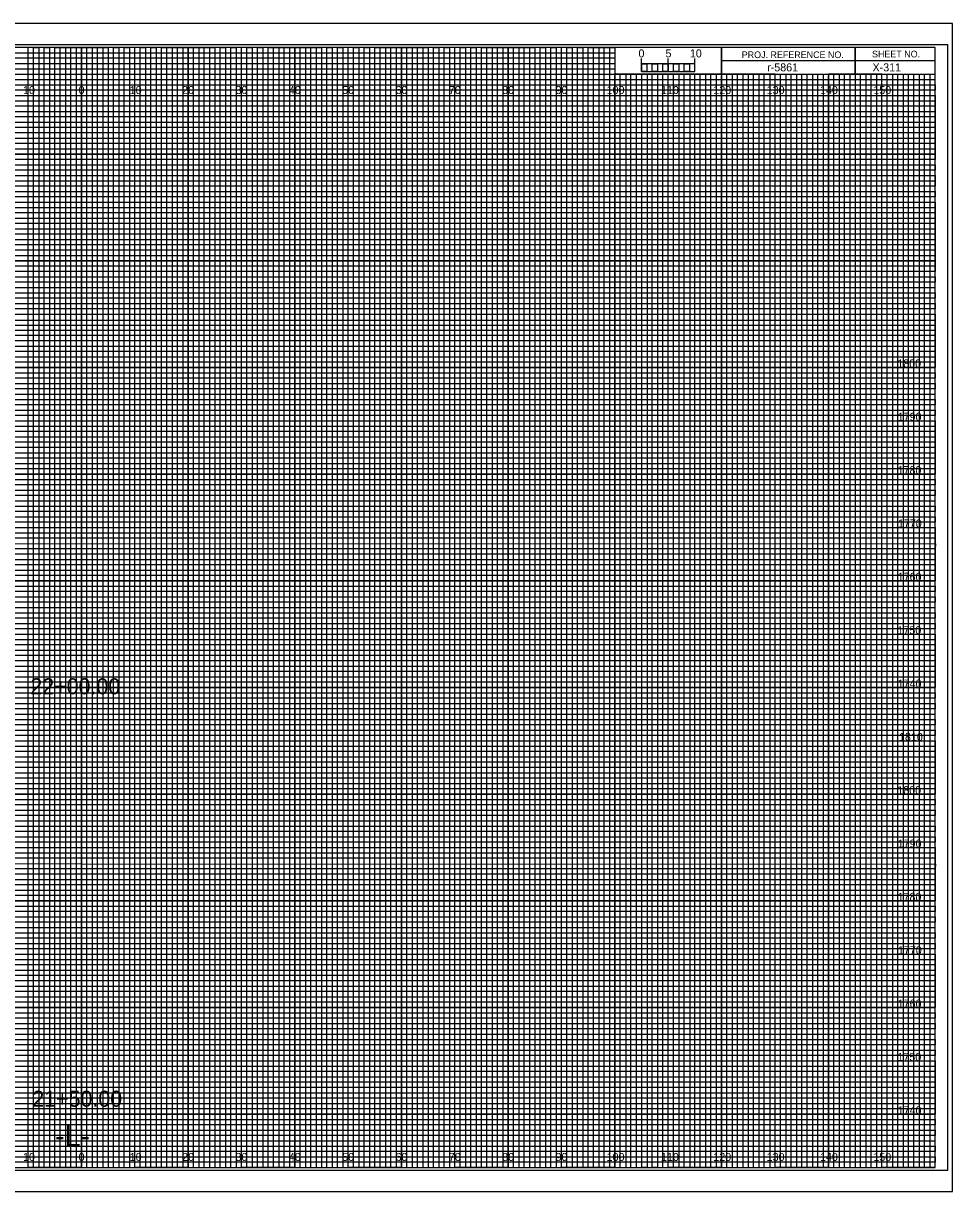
# Model space of a CAD drawing. Extents: x -15 to 323, y -5 to 6170.
# Drawn here: x 149.1 to 323.3, y 1535.5 to 1754.5 of the extents above; entities that cross this region are included whole.
import ezdxf

# ---------------------------------------------------------------- set-up
doc = ezdxf.new("R2010")
doc.units = 0
for name, color, linetype in [('Prop XS Alignment Label', 7, 'Continuous'), ('Prop XS Bar Scale Labels', 7, 'Continuous'), ('Prop XS DDE', 7, 'Continuous'), ('Prop XS DDE Earthwork Shape', 7, 'Continuous'), ('Prop XS DDE Slope Text', 7, 'Continuous'), ('Prop XS DDE Text', 7, 'Continuous'), ('Prop XS Earthwork Shape', 7, 'Continuous'), ('Prop XS Noise Wall', 7, 'Continuous'), ('Prop XS Project Number', 7, 'Continuous'), ('Prop XS Retaining Wall', 7, 'Continuous'), ('Prop XS Station Labels', 7, 'Continuous'), ('Prop XS Temporary Shoring', 7, 'Continuous'), ('Scratch_Level_3', 7, 'Continuous'), ('Scratch_Level_7', 7, 'Continuous'), ('Scratch_Level_8', 7, 'Continuous'), ('Sheet Cross Section Grid Minor 1 CELL', 7, 'Continuous')]:
    doc.layers.add(name, color=color, linetype=linetype)

msp = doc.modelspace()

# ---------------------------------------------------------------- linework, layer by layer
at = {"layer": 'Prop XS Alignment Label'}
for p, q in [((265, 1745.49), (265, 1747.9)), ((265, 1746.9), (265, 1747.9)), ((270, 1745.49), (270, 1747.9)), ((275, 1745.49), (275, 1747.9)), ((275, 1746.9), (275, 1747.9))]:
    msp.add_line(p, q, dxfattribs=at)
for points in [[(275, 1746.9), (265, 1746.9), (265, 1745.49), (275, 1745.49)], [(265, 1746.9), (266, 1746.9), (266, 1745.49), (265, 1745.49)], [(267, 1746.9), (268, 1746.9), (268, 1745.49), (267, 1745.49)], [(269, 1746.9), (270, 1746.9), (270, 1745.49), (269, 1745.49)], [(271, 1746.9), (272, 1746.9), (272, 1745.49), (271, 1745.49)], [(273, 1746.9), (274, 1746.9), (274, 1745.49), (273, 1745.49)]]:
    msp.add_lwpolyline(points, close=True, dxfattribs=at)
at = {"layer": 'Prop XS DDE'}
msp.add_lwpolyline([(-13.4, 1535.5), (323.3, 1535.5), (323.3, 1754.5), (-13.4, 1754.5)], close=True, dxfattribs=at)
at = {"layer": 'Prop XS DDE Slope Text'}
msp.add_lwpolyline([(-10.8, 1539.5), (322.4, 1539.5), (322.4, 1750.5), (-10.8, 1750.5)], close=True, dxfattribs=at)
at = {"layer": 'Prop XS DDE Text'}
for p, q in [((150, 1540), (150, 1750)), ((160, 1540), (160, 1750)), ((170, 1540), (170, 1750)), ((180, 1540), (180, 1750)), ((190, 1540), (190, 1750)), ((200, 1540), (200, 1750)), ((210, 1540), (210, 1750)), ((220, 1540), (220, 1750)), ((230, 1540), (230, 1750)), ((240, 1540), (240, 1750)), ((250, 1540), (250, 1750)), ((260, 1540), (260, 1744.69)), ((270, 1540), (270, 1744.69)), ((280, 1540), (280, 1744.69)), ((290, 1540), (290, 1744.69)), ((300, 1540), (300, 1744.69)), ((310, 1540), (310, 1744.69)), ((0, 1740), (320, 1740)), ((0, 1730), (320, 1730)), ((0, 1720), (320, 1720)), ((0, 1710), (320, 1710)), ((0, 1700), (320, 1700)), ((0, 1690), (320, 1690)), ((0, 1680), (320, 1680)), ((0, 1670), (320, 1670)), ((0, 1660), (320, 1660)), ((0, 1650), (320, 1650)), ((0, 1640), (320, 1640)), ((0, 1630), (320, 1630)), ((0, 1620), (320, 1620)), ((0, 1610), (320, 1610)), ((0, 1600), (320, 1600)), ((0, 1590), (320, 1590)), ((0, 1580), (320, 1580)), ((0, 1570), (320, 1570)), ((0, 1560), (320, 1560)), ((0, 1550), (320, 1550))]:
    msp.add_line(p, q, dxfattribs=at)
at = {"layer": 'Prop XS Earthwork Shape'}
for p, q in [((150, 1750), (140, 1750)), ((150, 1540), (150, 1750)), ((170, 1750), (160, 1750)), ((160, 1750), (160, 1540)), ((170, 1540), (170, 1750)), ((190, 1750), (180, 1750)), ((180, 1750), (180, 1540)), ((190, 1540), (190, 1750)), ((210, 1750), (200, 1750)), ((200, 1750), (200, 1540)), ((210, 1540), (210, 1750)), ((230, 1750), (220, 1750)), ((220, 1750), (220, 1540)), ((230, 1540), (230, 1750)), ((250, 1750), (240, 1750)), ((240, 1750), (240, 1540)), ((250, 1540), (250, 1750)), ((260, 1750), (260, 1540)), ((270, 1540), (270, 1745)), ((290, 1745), (280, 1745)), ((280, 1745), (280, 1540)), ((290, 1540), (290, 1745)), ((310, 1745), (300, 1745)), ((300, 1745), (300, 1540)), ((310, 1540), (310, 1745)), ((160, 1540), (150, 1540)), ((180, 1540), (170, 1540)), ((200, 1540), (190, 1540)), ((220, 1540), (210, 1540)), ((240, 1540), (230, 1540)), ((260, 1540), (250, 1540)), ((280, 1540), (270, 1540)), ((300, 1540), (290, 1540)), ((320, 1540), (310, 1540)), ((320, 1540), (320, 1540))]:
    msp.add_line(p, q, dxfattribs=at)
for points in [[(0, 1740), (320, 1740), (320, 1730), (0, 1730)], [(0, 1720), (320, 1720), (320, 1710), (0, 1710)], [(0, 1700), (320, 1700), (320, 1690), (0, 1690)], [(0, 1680), (320, 1680), (320, 1670), (0, 1670)], [(0, 1660), (320, 1660), (320, 1650), (0, 1650)], [(0, 1640), (320, 1640), (320, 1630), (0, 1630)], [(0, 1620), (320, 1620), (320, 1610), (0, 1610)], [(0, 1600), (320, 1600), (320, 1590), (0, 1590)], [(0, 1580), (320, 1580), (320, 1570), (0, 1570)], [(0, 1560), (320, 1560), (320, 1550), (0, 1550)]]:
    msp.add_lwpolyline(points, dxfattribs=at)
at = {"layer": 'Prop XS Noise Wall'}
for p, q in [((305, 1750), (305, 1745)), ((305, 1745), (305, 1750)), ((280, 1747.5), (280, 1745)), ((320, 1747.49), (280, 1747.49)), ((280, 1745), (320, 1745))]:
    msp.add_line(p, q, dxfattribs=at)
for points in [[(320, 1750), (0, 1750), (0, 1540), (320, 1540)], [(280, 1750), (260, 1750), (260, 1745.03), (280, 1745.03)], [(320, 1750), (280, 1750), (280, 1745), (320, 1745)]]:
    msp.add_lwpolyline(points, close=True, dxfattribs=at)
at = {"layer": 'Prop XS Retaining Wall'}
for p, q in [((267, 1745), (266.01, 1745)), ((266.01, 1745), (266.01, 1540)), ((267, 1540), (267, 1745)), ((269, 1745), (268, 1745)), ((268, 1745), (268, 1540)), ((269, 1540), (269, 1745)), ((266.01, 1540), (265, 1540)), ((268, 1540), (267, 1540))]:
    msp.add_line(p, q, dxfattribs=at)
for points in [[(150, 1540), (151, 1540), (151, 1750), (152, 1750), (152, 1540)], [(152, 1540), (153, 1540), (153, 1750), (154, 1750), (154, 1540)], [(155, 1540), (156, 1540), (156, 1750), (157, 1750), (157, 1540)], [(157, 1540), (158, 1540), (158, 1750), (159, 1750), (159, 1540)], [(160, 1540), (161, 1540), (161, 1750), (162, 1750), (162, 1540)], [(162, 1540), (163, 1540), (163, 1750), (164, 1750), (164, 1540)], [(165, 1540), (166, 1540), (166, 1750), (167, 1750), (167, 1540)], [(167, 1540), (168, 1540), (168, 1750), (169, 1750), (169, 1540)], [(170, 1540), (171, 1540), (171, 1750), (172, 1750), (172, 1540)], [(172, 1540), (173, 1540), (173, 1750), (174, 1750), (174, 1540)], [(175, 1540), (176, 1540), (176, 1750), (177, 1750), (177, 1540)], [(177, 1540), (178, 1540), (178, 1750), (179, 1750), (179, 1540)], [(180, 1540), (181, 1540), (181, 1750), (182, 1750), (182, 1540)], [(182, 1540), (183, 1540), (183, 1750), (184, 1750), (184, 1540)], [(185, 1540), (186, 1540), (186, 1750), (187, 1750), (187, 1540)], [(187, 1540), (188, 1540), (188, 1750), (189, 1750), (189, 1540)], [(190, 1540), (191, 1540), (191, 1750), (192, 1750), (192, 1540)], [(192, 1540), (193, 1540), (193, 1750), (194, 1750), (194, 1540)], [(195, 1540), (196, 1540), (196, 1750), (197, 1750), (197, 1540)], [(197, 1540), (198, 1540), (198, 1750), (199, 1750), (199, 1540)], [(200, 1540), (201, 1540), (201, 1750), (202, 1750), (202, 1540)], [(202, 1540), (203, 1540), (203, 1750), (204, 1750), (204, 1540)], [(205, 1540), (206, 1540), (206, 1750), (207, 1750), (207, 1540)], [(207, 1540), (208, 1540), (208, 1750), (209, 1750), (209, 1540)], [(210, 1540), (211, 1540), (211, 1750), (212, 1750), (212, 1540)], [(212, 1540), (213, 1540), (213, 1750), (214, 1750), (214, 1540)], [(215, 1540), (216, 1540), (216, 1750), (217, 1750), (217, 1540)], [(217, 1540), (218, 1540), (218, 1750), (219, 1750), (219, 1540)], [(220, 1540), (221, 1540), (221, 1750), (222, 1750), (222, 1540)], [(222, 1540), (223, 1540), (223, 1750), (224, 1750), (224, 1540)], [(225, 1540), (226, 1540), (226, 1750), (227, 1750), (227, 1540)], [(227, 1540), (228, 1540), (228, 1750), (229, 1750), (229, 1540)], [(230, 1540), (231, 1540), (231, 1750), (232, 1750), (232, 1540)], [(232, 1540), (233, 1540), (233, 1750), (234, 1750), (234, 1540)], [(235, 1540), (236, 1540), (236, 1750), (237, 1750), (237, 1540)], [(237, 1540), (238, 1540), (238, 1750), (239, 1750), (239, 1540)], [(240, 1540), (241, 1540), (241, 1750), (242, 1750), (242, 1540)], [(242, 1540), (243, 1540), (243, 1750), (244, 1750), (244, 1540)], [(245, 1540), (246, 1540), (246, 1750), (247, 1750), (247, 1540)], [(247, 1540), (248, 1540), (248, 1750), (249, 1750), (249, 1540)], [(250, 1540), (251, 1540), (251, 1750), (252, 1750), (252, 1540)], [(252, 1540), (253, 1540), (253, 1750), (254, 1750), (254, 1540)], [(255, 1540), (256, 1540), (256, 1750), (257, 1750), (257, 1540)], [(257, 1540), (258, 1540), (258, 1750), (259, 1750), (259, 1540)], [(260, 1540), (261, 1540), (261, 1745), (262.02, 1745), (262.02, 1540)], [(262, 1540), (263, 1540), (263, 1745), (263.99, 1745), (263.99, 1540)], [(270, 1540), (270.98, 1540), (270.98, 1745), (272, 1745), (272, 1540)], [(272, 1540), (273, 1540), (273, 1745), (274.05, 1745), (274.05, 1540)], [(275, 1540), (276, 1540), (276, 1745), (277, 1745), (277, 1540)], [(277, 1540), (278, 1540), (278, 1745), (279, 1745), (279, 1540)], [(280, 1540), (281, 1540), (281, 1745), (282, 1745), (282, 1540)], [(282, 1540), (283, 1540), (283, 1745), (284, 1745), (284, 1540)], [(285, 1540), (286, 1540), (286, 1745), (287, 1745), (287, 1540)], [(287, 1540), (288, 1540), (288, 1745), (289, 1745), (289, 1540)], [(290, 1540), (291, 1540), (291, 1745), (292, 1745), (292, 1540)], [(292, 1540), (293, 1540), (293, 1745), (294, 1745), (294, 1540)], [(295, 1540), (296, 1540), (296, 1745), (297, 1745), (297, 1540)], [(297, 1540), (298, 1540), (298, 1745), (299, 1745), (299, 1540)], [(300, 1540), (301, 1540), (301, 1745), (302, 1745), (302, 1540)], [(302, 1540), (303, 1540), (303, 1745), (304, 1745), (304, 1540)], [(305, 1540), (306, 1540), (306, 1745), (307, 1745), (307, 1540)], [(307, 1540), (308, 1540), (308, 1745), (309, 1745), (309, 1540)], [(310, 1540), (311, 1540), (311, 1745), (312, 1745), (312, 1540)], [(312, 1540), (313, 1540), (313, 1745), (314, 1745), (314, 1540)], [(315, 1540), (316, 1540), (316, 1745), (317, 1745), (317, 1540)], [(317, 1540), (318, 1540), (318, 1745), (319, 1745), (319, 1540)]]:
    msp.add_lwpolyline(points, dxfattribs=at)
at = {"layer": 'Prop XS Station Labels'}
for points in [[(145, 1540), (155, 1540), (155, 1750), (165, 1750), (165, 1540), (175, 1540), (175, 1750), (185, 1750), (185, 1540), (195, 1540), (195, 1750), (205, 1750), (205, 1540), (215, 1540), (215, 1750), (225, 1750), (225, 1540), (235, 1540), (235, 1750), (245, 1750), (245, 1540), (255, 1540), (255, 1750), (259.93, 1750), (260, 1750), (260, 1745), (264.99, 1745), (264.99, 1540), (275, 1540), (275, 1745), (285, 1745), (285, 1540), (295, 1540), (295, 1745), (305, 1745), (305, 1540), (315, 1540), (315, 1745)], [(0, 1745), (275, 1745)], [(0, 1725), (320, 1725), (320, 1735), (0, 1735)], [(0, 1705), (320, 1705), (320, 1715), (0, 1715)], [(0, 1685), (320, 1685), (320, 1695), (0, 1695)], [(0, 1665), (320, 1665), (320, 1675), (0, 1675)], [(0, 1645), (320, 1645), (320, 1655), (0, 1655)], [(0, 1625), (320, 1625), (320, 1635), (0, 1635)], [(0, 1605), (320, 1605), (320, 1615), (0, 1615)], [(0, 1585), (320, 1585), (320, 1595), (0, 1595)], [(0, 1565), (320, 1565), (320, 1575), (0, 1575)], [(0, 1545), (320, 1545), (320, 1555), (0, 1555)]]:
    msp.add_lwpolyline(points, dxfattribs=at)
at = {"layer": 'Scratch_Level_7'}
for p, q in [((323.3, 1754.5), (-13.4, 1754.5)), ((-13.4, 1535.5), (323.3, 1535.5))]:
    msp.add_line(p, q, dxfattribs=at)
at = {"layer": 'Sheet Cross Section Grid Minor 1 CELL'}
for p, q in [((0, 1749), (260, 1749)), ((260, 1747.98), (0, 1747.98)), ((260, 1749), (260, 1747.98)), ((0, 1747), (260, 1747)), ((260, 1745.89), (0, 1745.89)), ((260, 1747), (260, 1745.89)), ((0, 1744), (320, 1744))]:
    msp.add_line(p, q, dxfattribs=at)
for points in [[(0, 1743), (270, 1743), (320, 1743), (320, 1742), (0, 1742)], [(0, 1741), (320, 1741), (320, 1739), (0, 1739)], [(0, 1738), (320, 1738), (320, 1737), (0, 1736.98)], [(0, 1736), (320, 1736), (320, 1734), (0, 1734)], [(0, 1733), (320, 1733), (320, 1732), (0, 1732)], [(0, 1731), (320, 1731), (320, 1729), (0, 1729)], [(0, 1728), (320, 1728), (320, 1727), (0, 1727)], [(0, 1726), (320, 1726), (320, 1724), (0, 1724)], [(0, 1723), (320, 1723), (320, 1722), (0, 1722)], [(0, 1721), (320, 1721), (320, 1719), (0, 1719)], [(0, 1718), (320, 1718), (320, 1717), (0, 1717)], [(0, 1716), (320, 1716), (320, 1713.95), (320, 1713), (320, 1712), (0, 1712)], [(0, 1714), (320, 1714), (320, 1713), (0, 1713)], [(0, 1711), (320, 1711), (320, 1709), (0, 1709.03)], [(0, 1709.03), (320, 1709), (320, 1708), (0, 1708)], [(0, 1707), (320, 1707), (320, 1706), (0, 1706)], [(0, 1704), (320, 1704), (320, 1703), (0, 1703)], [(0, 1702), (320, 1702), (320, 1701), (0, 1701)], [(-0.07, 1698.89), (320, 1698.89), (320, 1697.88), (-0.07, 1697.88)], [(0, 1697), (320, 1697), (320, 1696), (0, 1696)], [(0, 1694), (320, 1694), (320, 1693), (0, 1693)], [(0, 1692), (320, 1692), (320, 1691), (0, 1691)], [(0, 1689), (320, 1689), (320, 1688), (0, 1688)], [(0, 1687), (320, 1687), (320, 1686), (0, 1686)], [(0, 1684), (320, 1684), (320, 1683), (0, 1683)], [(0, 1682), (320, 1682), (320, 1681), (0, 1681)], [(0, 1679), (320, 1679), (319.99, 1677.98), (0, 1678)], [(0, 1677), (320, 1677), (320, 1676), (0, 1676)], [(0, 1674), (320, 1674), (320, 1673), (0, 1673)], [(0, 1672), (320, 1672), (320, 1671), (0, 1671)], [(0, 1669), (320, 1669), (320, 1668), (0, 1668)], [(0, 1667), (320, 1667), (320, 1666), (0, 1666)], [(0, 1664), (320, 1664), (320, 1663), (0, 1663)], [(0, 1662), (320, 1662), (320, 1661), (0, 1661)], [(0, 1659), (320, 1659), (320, 1658), (0, 1658)], [(0, 1656.99), (320.07, 1656.91), (320, 1656), (0, 1656)], [(0, 1654), (320, 1654), (320, 1653), (0, 1653)], [(0, 1652), (320, 1652), (320, 1651), (0, 1651)], [(0, 1649), (320, 1649), (320, 1648), (0, 1648)], [(0, 1647), (320, 1647), (320, 1646), (0, 1646)], [(0, 1644), (320, 1644), (320, 1643), (0, 1643)], [(0, 1642), (320, 1642), (320, 1641), (0, 1641)], [(0, 1639), (320, 1639), (320, 1638), (0, 1638)], [(0, 1637), (320, 1637), (320, 1636), (0, 1636)], [(0, 1634), (320, 1634), (320, 1633), (0, 1633)], [(0, 1632), (320, 1632), (320, 1631), (0, 1631)], [(0, 1629), (320, 1629), (320, 1628), (0, 1628)], [(0, 1627), (320, 1627), (320, 1626), (0, 1626)], [(0, 1624), (320, 1624), (320, 1623), (0, 1623)], [(0, 1622), (320, 1622), (320, 1621), (0, 1621)], [(0, 1619), (320, 1619), (319.99, 1617.98), (0, 1618)], [(0, 1617), (320, 1617), (320, 1616), (0, 1616)], [(0, 1614), (320, 1614), (320, 1613), (0, 1613)], [(0, 1612), (320, 1612), (320, 1611), (0, 1611)], [(0, 1609), (320, 1609), (320, 1608), (0, 1608)], [(0, 1607), (320, 1607), (320, 1606), (0, 1606)], [(0, 1604), (320, 1604), (320, 1603), (0, 1603)], [(0, 1602), (320, 1602), (320, 1601), (0, 1601)], [(0, 1599), (320, 1599), (320, 1598), (0, 1598)], [(0, 1596.99), (320.07, 1596.91), (320, 1596), (0, 1596)], [(0, 1594), (320, 1594), (320, 1593), (0, 1593)], [(0, 1592), (320, 1592), (320, 1591), (0, 1591)], [(0, 1589), (320, 1589), (320, 1588), (0, 1588)], [(0, 1587), (320, 1587), (320, 1586), (0, 1586)], [(0, 1584), (320, 1584), (320, 1583), (0, 1583)], [(0, 1582), (320, 1582), (320, 1581), (0, 1581)], [(0, 1579), (320, 1579), (320, 1578), (0, 1578)], [(0, 1577), (320, 1577), (320, 1576), (0, 1576)], [(0, 1574), (320, 1574), (320, 1573), (0, 1573)], [(0, 1572), (320, 1572), (320, 1571), (0, 1571)], [(0, 1569), (320, 1569), (320, 1568), (0, 1568)], [(0, 1567), (320, 1567), (320, 1566), (0, 1566)], [(0, 1564), (320, 1564), (320, 1563), (0, 1563)], [(0, 1562), (320, 1562), (320, 1561), (0, 1561)], [(0, 1559), (320, 1559), (320, 1558), (0, 1558)], [(0, 1557), (320, 1557), (320, 1556), (0, 1556)], [(0, 1554), (320, 1554), (320, 1553), (0, 1553)], [(0, 1552), (320, 1552), (320, 1551), (0, 1551)], [(0, 1549), (320, 1549), (320, 1548), (0, 1548)], [(0, 1547), (320, 1547), (320, 1546), (0, 1546)], [(0, 1544), (320, 1544), (320, 1543), (0, 1543)], [(0, 1542), (320, 1542), (320, 1541), (0, 1541)]]:
    msp.add_lwpolyline(points, dxfattribs=at)

# ---------------------------------------------------------------- texts
at = {"layer": 'Prop XS Alignment Label'}
for s, height, p in [('0', 1.5, (264.41, 1748.12)), ('-L-', 4, (155.06, 1544))]:
    msp.add_text(s, height=height, dxfattribs=at).set_placement(p)
at = {"layer": 'Prop XS Bar Scale Labels'}
for s, p in [('5', (269.47, 1748.12)), ('10', (274.04, 1748.12))]:
    msp.add_text(s, height=1.5, dxfattribs=at).set_placement(p)
at = {"layer": 'Prop XS DDE Earthwork Shape'}
msp.add_text('X-311', height=1.5, dxfattribs=at).set_placement((308.28, 1745.5))
at = {"layer": 'Prop XS Noise Wall'}
for s, p in [('PROJ. REFERENCE NO.', (283.77, 1747.99)), ('SHEET NO.', (308.19, 1748.12))]:
    msp.add_text(s, height=1.25, dxfattribs=at).set_placement(p)
at = {"layer": 'Prop XS Project Number'}
msp.add_text('r-5861', height=1.5, dxfattribs=at).set_placement((288.53, 1745.5))
at = {"layer": 'Prop XS Temporary Shoring'}
for s, p in [('22+00.00', (150.41, 1628.73)), ('21+50.00', (150.77, 1551.42))]:
    msp.add_text(s, height=3, dxfattribs=at).set_placement(p)
at = {"layer": 'Scratch_Level_3'}
for s, p in [('1800', (312.92, 1690)), ('1790', (313, 1680)), ('1780', (312.98, 1670)), ('1770', (313.04, 1660)), ('1760', (313, 1650)), ('1750', (312.96, 1640)), ('1740', (313, 1630)), ('1810', (313.25, 1620)), ('1800', (312.92, 1610)), ('1790', (313, 1600)), ('1780', (312.98, 1590)), ('1770', (313.04, 1580)), ('1760', (313, 1570)), ('1750', (312.96, 1560)), ('1740', (313, 1550))]:
    msp.add_text(s, height=1.5, dxfattribs=at).set_placement(p)
at = {"layer": 'Scratch_Level_8'}
for s, p in [('10', (149.04, 1741.25)), ('0', (159.45, 1741.25)), ('0', (159.45, 1741.25)), ('10', (169.04, 1741.25)), ('20', (178.86, 1741.25)), ('30', (188.86, 1741.25)), ('40', (198.86, 1741.25)), ('50', (208.86, 1741.25)), ('60', (218.86, 1741.25)), ('70', (228.86, 1741.25)), ('80', (238.86, 1741.25)), ('90', (248.86, 1741.25)), ('100', (258.44, 1741.25)), ('110', (268.62, 1741.25)), ('120', (278.44, 1741.25)), ('130', (288.44, 1741.25)), ('140', (298.44, 1741.25)), ('150', (308.44, 1741.25)), ('10', (149.04, 1541.25)), ('0', (159.45, 1541.25)), ('0', (159.45, 1541.25)), ('10', (169.04, 1541.25)), ('20', (178.86, 1541.25)), ('30', (188.86, 1541.25)), ('40', (198.86, 1541.25)), ('50', (208.86, 1541.25)), ('60', (218.86, 1541.25)), ('70', (228.86, 1541.25)), ('80', (238.86, 1541.25)), ('90', (248.86, 1541.25)), ('100', (258.44, 1541.25)), ('110', (268.62, 1541.25)), ('120', (278.44, 1541.25)), ('130', (288.44, 1541.25)), ('140', (298.44, 1541.25)), ('150', (308.44, 1541.25))]:
    msp.add_text(s, height=1.5, dxfattribs=at).set_placement(p)

doc.saveas('drawing.dxf')
